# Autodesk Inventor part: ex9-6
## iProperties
Shininess: 64.0
Length Units: 11272
Angle Units: 11279
Time Units: 11290
Mass Units: 11286
Length Display Precision: 3
Angle Display Precision: 2
Compacted: True
Part Number: ex9-6
Document SubType Name: Sheet Metal
Created: 2002-11
Designer: Elise Moss
Density: 0.0
Volumn: 0.0
Area: 0.0
PropertySet Name: Model Information
Control State: 0
Master: False
Checked Out: False
Author: Elise Moss
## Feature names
1. Plate1
2. Bend1
3. Plate2
4. Bend2
5. Cut1
